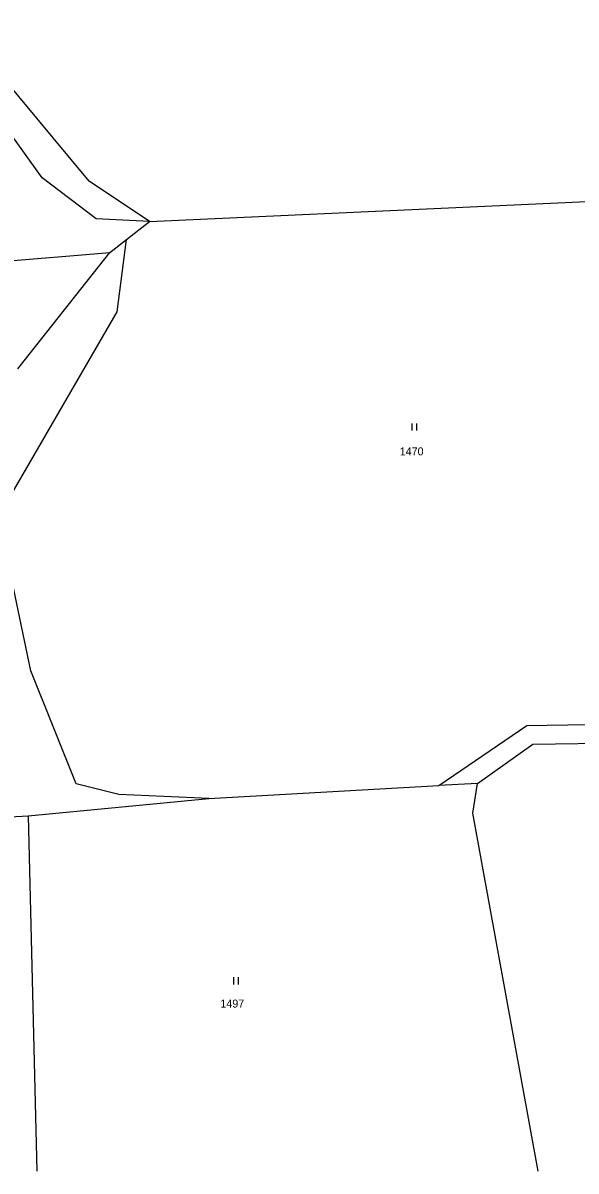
# Model space of a CAD drawing. Extents: x -520431 to -517205, y -1075927 to -1074013.
# Drawn here: x -517833.2 to -517715.9, y -1075925.4 to -1075681.5 of the extents above; entities that cross this region are included whole.
import ezdxf

# ---------------------------------------------------------------- set-up
doc = ezdxf.new("R2010")
doc.units = 0
for name, color, linetype in [('Hranice parcel', 7, 'Continuous'), ('Parcelní čísla', 7, 'Continuous'), ('Značky kultur', 7, 'Continuous')]:
    doc.layers.add(name, color=color, linetype=linetype)

msp = doc.modelspace()

# ---------------------------------------------------------------- linework, layer by layer
at = {"layer": 'Hranice parcel'}
for p, q in [((-517806.36, -1075723.7), (-517649.3, -1075716.5)), ((-517811.29, -1075727.53), (-517806.36, -1075723.7)), ((-517814.81, -1075730.26), (-517811.29, -1075727.53)), ((-517851.25, -1075733.31), (-517814.81, -1075730.26)), ((-517834.35, -1075754.98), (-517814.81, -1075730.26)), ((-517793.8, -1075846.26), (-517744.95, -1075843.48)), ((-517736.78, -1075843.02), (-517744.95, -1075843.48)), ((-517832.14, -1075849.94), (-517793.8, -1075846.26)), ((-517853.06, -1075850.94), (-517832.14, -1075849.94))]:
    msp.add_line(p, q, dxfattribs=at)
for points in [[(-517806.36, -1075723.7), (-517819.22, -1075715.13), (-517837.94, -1075692.54), (-517847.81, -1075659.24), (-517846.75, -1075648.71), (-517851.31, -1075636.96), (-517844.3, -1075608.48), (-517829.48, -1075581.32), (-517717.18, -1075576.77), (-517716.55, -1075569.07)], [(-517806.36, -1075723.7), (-517817.71, -1075723.13), (-517829.2, -1075714.45), (-517841.94, -1075696.76)], [(-517793.8, -1075846.26), (-517812.91, -1075845.37), (-517821.92, -1075843.14), (-517831.6, -1075819.12), (-517835.29, -1075801.49), (-517840.01, -1075788.94), (-517813.28, -1075742.89), (-517811.29, -1075727.53)], [(-517744.95, -1075843.48), (-517726.31, -1075830.74), (-517687.17, -1075830.11), (-517675.91, -1075827.57), (-517663.26, -1075821.34), (-517661.1, -1075815.74)], [(-517736.78, -1075843.02), (-517725.01, -1075834.72), (-517686.69, -1075834.1), (-517674.57, -1075831.37), (-517660.19, -1075824.32)], [(-517723.89, -1075925.35), (-517737.73, -1075849.35), (-517736.78, -1075843.02)], [(-517832.14, -1075849.94), (-517830.27, -1075925.35)]]:
    msp.add_lwpolyline(points, dxfattribs=at)
at = {"layer": 'Značky kultur'}
for p, q in [((-517750.66, -1075768.09), (-517750.66, -1075766.59)), ((-517749.66, -1075768.09), (-517749.66, -1075766.59)), ((-517788.51, -1075885.71), (-517788.51, -1075884.21)), ((-517787.51, -1075885.71), (-517787.51, -1075884.21))]:
    msp.add_line(p, q, dxfattribs=at)

# ---------------------------------------------------------------- texts
at = {"layer": 'Parcelní čísla'}
for s, p in [('1470', (-517753.27, -1075773.37)), ('1497', (-517791.34, -1075890.64))]:
    msp.add_text(s, height=1.7, dxfattribs=at).set_placement(p)

doc.saveas('drawing.dxf')
